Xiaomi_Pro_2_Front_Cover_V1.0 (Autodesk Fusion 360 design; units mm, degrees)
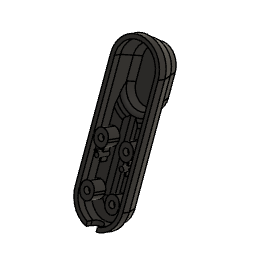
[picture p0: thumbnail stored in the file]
sketch "Skizze1" plane through (0, 0, 0) normal (0, 0, 1) x axis (1, 0, 0)
  line L1 (-32.75, -15) -> (32.75, -15)
  line L2 (32.75, 15) -> (-32.75, 15)
  line L3 (-47.75, 15) -> (47.75, -15)
  line L4 (47.75, 15) -> (-47.75, -15)
  arc A1 centre (-32.75, 0) radius 15 clockwise from (-47.75, 0) to (-32.75, 15)
  arc A2 centre (-32.75, 0) radius 15 clockwise from (-32.75, -15) to (-47.75, 0)
  arc A3 centre (32.75, 0) radius 15 clockwise from (32.75, 15) to (47.75, 0)
  arc A4 centre (32.75, 0) radius 15 clockwise from (47.75, 0) to (32.75, -15)
  point P6 (0, 0)
  point P1 (0, 0)
  point P4 (-47.75, 15)
  point P3 (-47.75, -15)
  point P8 (-47.75, 0)
  point P10 (-47.75, 0)
  point P5 (47.75, 15)
  point P2 (47.75, -15)
  point P14 (47.75, 0)
  point P16 (47.75, 0)
  horizontal L1
  parallel L1 L2
  coincident L3 P6
  coincident L4 P6
  coincident P1 P6
  coincident P4 L2
  tangent L2 A1
  coincident P3 L1
  tangent L1 A2
  coincident P8 P10
  coincident P5 L2
  tangent L2 A3
  coincident P2 L1
  tangent L1 A4
  coincident P14 P16
  dimension "d1" distance P4 P5 = 95.5
  dimension "d2" distance P3 P4 = 30
  dimension "d3" radius A1 = 15
  dimension "d4" radius A2 = 15
  dimension "d5" radius A3 = 15
  dimension "d6" radius A4 = 15
extrude "Extrusion1" new body sketch "Skizze1" profile of L1 L2 A1 A2 A3 A4 along normal blind 17
chamfer "Fase1" distance 5 distance 12.5
extrude "Extrusion2" cut of existing geometry blind -6 taper 22
sketch "Skizze2" plane through (0, 0, 11) normal (0, 0, 1) x axis (-1, 0, 0)
  line L1 (-32.75, 12.4) -> (32.75, 12.4)
  line L2 (32.75, -12.4) -> (-32.75, -12.4)
  line L3 (7.65, 0) -> (45.15, 0)
  line L4 (45.15, 12.4) -> (7.65, 12.4)
  line L5 (45.15, -12.4) -> (45.15, 12.4)
  line L6 (7.65, -12.4) -> (45.15, -12.4)
  line L7 (7.65, 12.4) -> (7.65, -12.4)
  line L8 (45.15, -12.4) -> (7.65, 12.4)
  line L9 (7.65, -12.4) -> (45.15, 12.4)
  line L10 (26.4, -12.4) -> (26.4, 0)
  line L11 (26.4, -12.4) -> (26.4, 0)
  arc A1 centre (-32.75, 0) radius 12.4 clockwise from (-32.75, -12.4) to (-32.75, 12.4)
  arc A2 centre (32.75, 0) radius 12.4 clockwise from (32.75, 12.4) to (32.75, -12.4)
  arc A3 centre (32.75, 0) radius 12.4 clockwise from (32.75, 12.4) to (32.75, -12.4)
  arc A4 centre (20.05, 0) radius 12.4 clockwise from (20.05, -12.4) to (20.05, 12.4)
  point P8 (45.15, 0)
  point P14 (26.4, 0)
  point P10 (7.65, 12.4)
  point P18 (26.4, 0)
  point P19 (26.4, -12.4)
  point P15 (32.75, -12.4)
  point P23 (20.05, -12.4)
  point P16 (32.75, 12.4)
  point P24 (20.05, 12.4)
  point P20 (26.4, 0)
  point P21 (26.4, -12.4)
  point P9 (7.65, 0)
  midpoint A2 P8
  horizontal L3
  horizontal L4
  perpendicular L4 L5
  parallel L4 L6
  parallel L5 L7
  coincident L8 P14
  coincident L9 P14
  coincident L1 P10
  midpoint L3 P14
  coincident P14 P18
  midpoint L6 P19
  symmetric P15 L10 P23
  symmetric P16 L10 P24
  symmetric A3 L10 A4
  symmetric P18 L10 P20
  symmetric P19 L10 P21
  dimension "d13" distance P8 P9 = 37.5
extrude "Extrusion3" add sketch "Skizze2" profile of L1 L2 A2 L3 L4 L6 A3 A4 along normal blind 6 taper -21.8
sketch "Skizze3" plane through (0, 0, 11) normal (0, 0, 1) x axis (-1, 0, 0)
  line L1 (-32.75, 12.4) -> (20.05, 12.4)
  line L2 (20.05, -12.4) -> (-32.75, -12.4)
  line L3 (13.0073, -11.4) -> (-32.75, -11.4)
  line L4 (-32.75, 11.4) -> (13.0073, 11.4)
  line L5 (-17, -4.5) -> (-17, 0)
  line L6 (7.4282, -4.5) -> (-17, -4.5)
  line L7 (-17, 4.5) -> (-17, 0)
  line L8 (7.4282, 4.5) -> (-17, 4.5)
  line L9 (-32.75, -4.5) -> (-17, -4.5)
  line L10 (-17, 4.5) -> (-32.75, 4.5)
  arc A1 centre (20.05, 0) radius 12.4 clockwise from (20.05, -12.4) to (20.05, 12.4)
  arc A2 centre (-32.75, 0) radius 12.4 clockwise from (-32.75, -12.4) to (-32.75, 12.4)
  arc A3 centre (20.05, 0) radius 13.4 clockwise from (13.0073, -11.4) to (13.0073, 11.4)
  arc A4 centre (-32.75, 0) radius 11.4 clockwise from (-32.75, -11.4) to (-32.75, 11.4)
  circle C1 centre (-32.75, 0) radius 4.5
  point P16 (7.4282, -4.5)
  point P18 (7.4282, 4.5)
  point P20 (-32.75, -4.5)
  point P21 (-32.75, 4.5)
  point P14 (-17, 0)
  point P15 (-17, -4.5)
  point P17 (-17, 4.5)
  perpendicular L3 L5
  coincident A3 P16
  perpendicular L5 L6
  perpendicular L6 L7
  coincident A3 P18
  perpendicular L7 L8
  concentric A2 C1
  coincident C1 P20
  tangent C1 L9
  perpendicular L5 L9
  coincident C1 P21
  tangent C1 L10
  dimension "d16" = -1
  dimension "d17" distance P14 P15 = 4.5
  dimension "d18" distance P14 P17 = 4.5
  dimension "d19" diameter C1 = 9
extrude "Extrusion4" cut sketch "Skizze3" profile of A3 L3 L4 A4 L6 L8 C1 L9 L10 against normal blind 1
fillet "Abrundung1" radius 0.5
fillet "Abrundung2" radius 0.5
shell "Schale" innerThickness 2.4
chamfer "Fase2" distance 1 distance 3
sketch "Skizze4" plane through (0, 0, 10) normal (0, 0, 1) x axis (-1, 0, 0)
  line L1 (-32.75, -4.5) -> (7.4282, -4.5)
  line L2 (7.4282, 4.5) -> (-32.75, 4.5)
  line L3 (-32.75, 11.4) -> (13.0073, 11.4)
  line L4 (13.0073, -11.4) -> (-32.75, -11.4)
  line L5 (-31.75, 0) -> (-47.75, 0)
  line L6 (-5.75, 0) -> (-31.75, 0)
  line L7 (7.4282, -4.5) -> (-32.75, -4.5)
  line L8 (-32.75, 4.5) -> (7.4282, 4.5)
  line L9 (-32.75, -11.4) -> (13.0073, -11.4)
  line L10 (13.0073, 11.4) -> (-32.75, 11.4)
  line L11 (-32.75, 7.9) -> (13.0073, 7.9)
  line L12 (13.0073, -7.9) -> (-32.75, -7.9)
  arc A1 centre (-32.75, 0) radius 4.5 clockwise from (-32.75, -4.5) to (-32.75, 4.5)
  arc A2 centre (20.05, 0) radius 13.4 clockwise from (7.4282, 4.5) to (13.0073, 11.4)
  arc A3 centre (-32.75, 0) radius 11.4 clockwise from (-32.75, -11.4) to (-32.75, 11.4)
  arc A4 centre (20.05, 0) radius 13.4 clockwise from (13.0073, -11.4) to (7.4282, -4.5)
  arc A5 centre (-32.75, 0) radius 15 clockwise from (-32.75, -15) to (-32.75, 15)
  arc A6 centre (-32.75, 0) radius 7.9 clockwise from (-32.75, -7.9) to (-32.75, 7.9)
  point P15 (-47.75, 0)
  point P31 (-5.75, -7.9)
  point P32 (-5.75, 7.9)
  point P33 (-31.75, -7.9)
  point P34 (-31.75, 7.9)
  point P16 (-31.75, 0)
  point P17 (-5.75, 0)
  midpoint A5 P15
  horizontal L5
  parallel L5 L6
  coincident L12 P31
  coincident L11 P32
  coincident L12 P33
  coincident L11 P34
  dimension "d31" distance P15 P16 = 16
  dimension "d32" distance P16 P17 = 26
  dimension "d33" = -3.5
sketch "Skizze5" plane through (0, 0, 7.6) normal (0, 0, -1) x axis (1, 0, 0)
  line L1 (-12.6556, 11.1751) -> (32.75, 11.1751)
  line L2 (32.75, 4.5) -> (-7.4282, 4.5)
  line L3 (-7.4282, -4.5) -> (32.75, -4.5)
  line L4 (32.75, -11.1751) -> (-12.6556, -11.1751)
  line L5 (5.025, 3.775) -> (6.475, 3.775)
  line L6 (0.875, 7.875) -> (0.875, 7.925)
  line L7 (6.475, 12.025) -> (5.025, 12.025)
  line L8 (10.625, 7.925) -> (10.625, 7.875)
  line L9 (0.875, 12.025) -> (10.625, 3.775)
  line L10 (10.625, 12.025) -> (0.875, 3.775)
  line L11 (32.475, 3.775) -> (31.025, 3.775)
  line L12 (36.625, 7.875) -> (36.625, 7.925)
  line L13 (31.025, 12.025) -> (32.475, 12.025)
  line L14 (26.875, 7.925) -> (26.875, 7.875)
  line L15 (36.625, 12.025) -> (26.875, 3.775)
  line L16 (26.875, 12.025) -> (36.625, 3.775)
  line L17 (5.025, -3.775) -> (6.475, -3.775)
  line L18 (0.875, -7.875) -> (0.875, -7.925)
  line L19 (6.475, -12.025) -> (5.025, -12.025)
  line L20 (10.625, -7.925) -> (10.625, -7.875)
  line L21 (0.875, -12.025) -> (10.625, -3.775)
  line L22 (10.625, -12.025) -> (0.875, -3.775)
  line L23 (31.025, -3.775) -> (32.475, -3.775)
  line L24 (26.875, -7.875) -> (26.875, -7.925)
  line L25 (32.475, -12.025) -> (31.025, -12.025)
  line L26 (36.625, -7.925) -> (36.625, -7.875)
  line L27 (26.875, -12.025) -> (36.625, -3.775)
  line L28 (36.625, -12.025) -> (26.875, -3.775)
  arc A1 centre (32.75, 0) radius 4.5 clockwise from (32.75, 4.5) to (32.75, -4.5)
  arc A2 centre (32.75, 0) radius 11.1751 clockwise from (32.75, 11.1751) to (32.75, -11.1751)
  arc A3 centre (5.025, 7.875) radius 4.15 clockwise from (0.875, 7.875) to (5.025, 12.025)
  arc A4 centre (5.025, 7.925) radius 4.15 clockwise from (5.025, 3.775) to (0.875, 7.925)
  arc A5 centre (6.475, 7.925) radius 4.15 clockwise from (10.625, 7.925) to (6.475, 3.775)
  arc A6 centre (6.475, 7.875) radius 4.15 clockwise from (6.475, 12.025) to (10.625, 7.875)
  arc A7 centre (31.025, 7.875) radius 4.15 clockwise from (26.875, 7.875) to (31.025, 12.025)
  arc A8 centre (32.475, 7.875) radius 4.15 clockwise from (32.475, 12.025) to (36.625, 7.875)
  arc A9 centre (32.475, 7.925) radius 4.15 clockwise from (36.625, 7.925) to (32.475, 3.775)
  arc A10 centre (31.025, 7.925) radius 4.15 clockwise from (31.025, 3.775) to (26.875, 7.925)
  arc A11 centre (32.475, -7.925) radius 4.15 clockwise from (32.475, -3.775) to (36.625, -7.925)
  arc A12 centre (32.475, -7.875) radius 4.15 clockwise from (36.625, -7.875) to (32.475, -12.025)
  arc A13 centre (31.025, -7.875) radius 4.15 clockwise from (31.025, -12.025) to (26.875, -7.875)
  arc A14 centre (31.025, -7.925) radius 4.15 clockwise from (26.875, -7.925) to (31.025, -3.775)
  arc A15 centre (6.475, -7.925) radius 4.15 clockwise from (6.475, -3.775) to (10.625, -7.925)
  arc A16 centre (5.025, -7.925) radius 4.15 clockwise from (0.875, -7.925) to (5.025, -3.775)
  arc A17 centre (5.025, -7.875) radius 4.15 clockwise from (5.025, -12.025) to (0.875, -7.875)
  arc A18 centre (6.475, -7.875) radius 4.15 clockwise from (10.625, -7.875) to (6.475, -12.025)
  arc A19 centre (-20.05, 0) radius 13.4 clockwise from (-12.6556, 11.1751) to (-7.4282, 4.5)
  arc A20 centre (-20.05, 0) radius 13.4 clockwise from (-7.4282, -4.5) to (-12.6556, -11.1751)
  point P19 (5.75, 7.9)
  point P12 (5.75, 7.9)
  point P24 (31.75, 7.9)
  point P11 (31.75, 7.9)
  point P29 (5.75, -7.9)
  point P13 (5.75, -7.9)
  point P34 (31.75, -7.9)
  point P14 (31.75, -7.9)
  point P17 (0.875, 12.025)
  point P16 (0.875, 3.775)
  point P15 (10.625, 3.775)
  point P18 (10.625, 12.025)
  point P23 (26.875, 12.025)
  point P22 (36.625, 12.025)
  point P21 (36.625, 3.775)
  point P20 (26.875, 3.775)
  point P30 (36.625, -3.775)
  point P33 (36.625, -12.025)
  point P32 (26.875, -12.025)
  point P31 (26.875, -3.775)
  point P25 (10.625, -3.775)
  point P26 (0.875, -3.775)
  point P27 (0.875, -12.025)
  point P28 (10.625, -12.025)
  horizontal L5
  perpendicular L5 L6
  parallel L5 L7
  parallel L6 L8
  coincident L9 P19
  coincident L10 P19
  coincident P12 P19
  horizontal L11
  perpendicular L11 L12
  parallel L11 L13
  parallel L12 L14
  coincident L15 P24
  coincident L16 P24
  coincident P11 P24
  horizontal L17
  perpendicular L17 L18
  parallel L17 L19
  parallel L18 L20
  coincident L21 P29
  coincident L22 P29
  coincident P13 P29
  horizontal L23
  perpendicular L23 L24
  parallel L23 L25
  parallel L24 L26
  coincident L27 P34
  coincident L28 P34
  coincident P14 P34
  coincident P17 L7
  coincident P17 L6
  tangent L7 A3
  tangent L6 A3
  coincident P16 L6
  coincident P16 L5
  tangent L6 A4
  tangent L5 A4
  equal A3 A4
  coincident P15 L5
  coincident P15 L8
  tangent L5 A5
  tangent L8 A5
  equal A3 A5
  coincident P18 L8
  coincident P18 L7
  tangent L8 A6
  tangent L7 A6
  equal A3 A6
  coincident P23 L14
  coincident P23 L13
  tangent L14 A7
  tangent L13 A7
  equal A3 A7
  coincident P22 L13
  coincident P22 L12
  tangent L13 A8
  tangent L12 A8
  equal A3 A8
  coincident P21 L12
  coincident P21 L11
  tangent L12 A9
  tangent L11 A9
  equal A3 A9
  coincident P20 L11
  coincident P20 L14
  tangent L11 A10
  tangent L14 A10
  equal A3 A10
  coincident P30 L23
  coincident P30 L26
  tangent L23 A11
  tangent L26 A11
  equal A3 A11
  coincident P33 L26
  coincident P33 L25
  tangent L26 A12
  tangent L25 A12
  equal A3 A12
  coincident P32 L25
  coincident P32 L24
  tangent L25 A13
  tangent L24 A13
  equal A3 A13
  coincident P31 L24
  coincident P31 L23
  tangent L24 A14
  tangent L23 A14
  equal A3 A14
  coincident P25 L20
  coincident P25 L17
  tangent L20 A15
  tangent L17 A15
  equal A3 A15
  coincident P26 L17
  coincident P26 L18
  tangent L17 A16
  tangent L18 A16
  equal A3 A16
  coincident P27 L18
  coincident P27 L19
  tangent L18 A17
  tangent L19 A17
  equal A3 A17
  coincident P28 L19
  coincident P28 L20
  tangent L19 A18
  tangent L20 A18
  equal A3 A18
  dimension "d39" distance P17 P18 = 9.75
  dimension "d40" distance P16 P17 = 8.25
  dimension "d41" distance P22 P23 = 9.75
  dimension "d42" distance P21 P22 = 8.25
  dimension "d43" distance P27 P28 = 9.75
  dimension "d44" distance P26 P27 = 8.25
  dimension "d45" distance P32 P33 = 9.75
  dimension "d46" distance P31 P32 = 8.25
  dimension "d47" radius A3 = 4.15
extrude "Extrusion5" add sketch "Skizze5" profile of L1 L2 A1 L3 L4 A2 L5 L7 L11 L13 L17 L19 L23 L25 A3 A4 A5 A6 A7 A8 A9 A10 A11 A12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 along normal blind 7.6 and against normal blind 1
sketch "Skizze6" plane through (0, 0, 0) normal (0, 0, -1) x axis (1, 0, 0)
  line L1 (-32.75, -12.6) -> (32.75, -12.6)
  line L2 (32.75, 12.6) -> (-32.75, 12.6)
  line L3 (32.75, -15) -> (-32.75, -15)
  line L4 (-32.75, 15) -> (32.75, 15)
  line L5 (5.025, 12.025) -> (6.475, 12.025)
  line L6 (31.025, 12.025) -> (32.475, 12.025)
  line L7 (32.475, -12.025) -> (31.025, -12.025)
  line L8 (6.475, -12.025) -> (5.025, -12.025)
  line L9 (5.375, 13.7209) -> (6.125, 13.7209)
  line L10 (5.375, 10.3291) -> (5.375, 13.7209)
  line L11 (6.125, 10.3291) -> (5.375, 10.3291)
  line L12 (6.125, 13.7209) -> (6.125, 10.3291)
  line L13 (5.375, 10.3291) -> (6.125, 13.7209)
  line L14 (6.125, 10.3291) -> (5.375, 13.7209)
  line L15 (6.125, 10.3291) -> (5.375, 13.7209)
  line L16 (5.375, 10.3291) -> (6.125, 13.7209)
  line L17 (5.375, 13.7209) -> (6.125, 13.7209)
  line L18 (5.375, 10.3291) -> (5.375, 13.7209)
  line L19 (6.125, 10.3291) -> (5.375, 10.3291)
  line L20 (6.125, 13.7209) -> (6.125, 10.3291)
  line L21 (31.375, 13.6) -> (32.125, 13.6)
  line L22 (31.375, 10.45) -> (31.375, 13.6)
  line L23 (32.125, 10.45) -> (31.375, 10.45)
  line L24 (32.125, 13.6) -> (32.125, 10.45)
  line L25 (31.375, 10.45) -> (32.125, 13.6)
  line L26 (32.125, 10.45) -> (31.375, 13.6)
  line L27 (31.375, -14) -> (32.125, -14)
  line L28 (31.375, -10.05) -> (31.375, -14)
  line L29 (32.125, -10.05) -> (31.375, -10.05)
  line L30 (32.125, -14) -> (32.125, -10.05)
  line L31 (31.375, -10.05) -> (32.125, -14)
  line L32 (32.125, -10.05) -> (31.375, -14)
  line L33 (5.375, -13.7758) -> (6.125, -13.7758)
  line L34 (5.375, -10.2742) -> (5.375, -13.7758)
  line L35 (6.125, -10.2742) -> (5.375, -10.2742)
  line L36 (6.125, -13.7758) -> (6.125, -10.2742)
  line L37 (5.375, -10.2742) -> (6.125, -13.7758)
  line L38 (6.125, -10.2742) -> (5.375, -13.7758)
  arc A1 centre (32.75, 0) radius 12.6 clockwise from (32.75, 12.6) to (32.75, -12.6)
  arc A2 centre (-32.75, 0) radius 12.6 clockwise from (-32.75, -12.6) to (-32.75, 12.6)
  arc A3 centre (-32.75, 0) radius 15 clockwise from (-32.75, -15) to (-32.75, 15)
  arc A4 centre (32.75, 0) radius 15 clockwise from (32.75, 15) to (32.75, -15)
  point P24 (5.75, 12.025)
  point P27 (5.75, 12.025)
  point P34 (31.75, 12.025)
  point P39 (31.75, -12.025)
  point P44 (5.75, -12.025)
  point P22 (5.375, 10.3291)
  point P23 (6.125, 10.3291)
  point P26 (5.375, 10.3291)
  point P28 (6.125, 10.3291)
  point P32 (31.375, 10.45)
  point P33 (32.125, 10.45)
  point P37 (31.375, -10.05)
  point P38 (32.125, -10.05)
  point P42 (5.375, -10.2742)
  point P43 (6.125, -10.2742)
  horizontal L9
  perpendicular L9 L10
  parallel L9 L11
  parallel L10 L12
  coincident L13 P24
  coincident L14 P24
  midpoint L5 P24
  horizontal L17
  perpendicular L17 L18
  parallel L17 L19
  parallel L18 L20
  coincident P27 L16
  coincident P27 L15
  horizontal L21
  perpendicular L21 L22
  parallel L21 L23
  parallel L22 L24
  coincident L25 P34
  coincident L26 P34
  midpoint L6 P34
  horizontal L27
  perpendicular L27 L28
  parallel L27 L29
  parallel L28 L30
  coincident L31 P39
  coincident L32 P39
  midpoint L7 P39
  horizontal L33
  perpendicular L33 L34
  parallel L33 L35
  parallel L34 L36
  coincident L37 P44
  coincident L38 P44
  midpoint L8 P44
  dimension "d52" distance P22 P23 = 0.75
  dimension "d53" distance P26 P28 = 0.75
  dimension "d54" distance P32 P33 = 0.75
  dimension "d55" distance P37 P38 = 0.75
  dimension "d56" distance P42 P43 = 0.75
extrude "Extrusion6" add sketch "Skizze6" profile of L1 L2 L5 L6 L7 L8 L9 L10 L11 L12 L17 L18 L19 L20 L21 L22 L23 L24 L27 L28 L29 L30 L33 L34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 against normal blind 6
sketch "Skizze7" plane through (0, 0, 0) normal (0, 0, -1) x axis (1, 0, 0)
  line L1 (-32.75, -12.6) -> (5.375, -12.6)
  line L2 (5.375, 12.6) -> (-32.75, 12.6)
  line L3 (5.375, 12.025) -> (5.375, 12.6)
  line L4 (5.025, 12.025) -> (5.375, 12.025)
  line L5 (6.475, 3.775) -> (5.025, 3.775)
  line L6 (6.125, 12.025) -> (6.475, 12.025)
  line L7 (6.125, 12.6) -> (6.125, 12.025)
  line L8 (31.375, 12.6) -> (6.125, 12.6)
  line L9 (31.375, 12.025) -> (31.375, 12.6)
  line L10 (31.025, 12.025) -> (31.375, 12.025)
  line L11 (32.475, 3.775) -> (31.025, 3.775)
  line L12 (32.125, 12.025) -> (32.475, 12.025)
  line L13 (32.125, 12.6) -> (32.125, 12.025)
  line L14 (32.75, 12.6) -> (32.125, 12.6)
  line L15 (32.125, -12.6) -> (32.75, -12.6)
  line L16 (32.125, -12.025) -> (32.125, -12.6)
  line L17 (32.475, -12.025) -> (32.125, -12.025)
  line L18 (31.025, -3.775) -> (32.475, -3.775)
  line L19 (31.375, -12.025) -> (31.025, -12.025)
  line L20 (31.375, -12.6) -> (31.375, -12.025)
  line L21 (6.125, -12.6) -> (31.375, -12.6)
  line L22 (6.125, -12.025) -> (6.125, -12.6)
  line L23 (6.475, -12.025) -> (6.125, -12.025)
  line L24 (5.025, -3.775) -> (6.475, -3.775)
  line L25 (5.375, -12.025) -> (5.025, -12.025)
  line L26 (5.375, -12.6) -> (5.375, -12.025)
  line L27 (32.75, -15) -> (-32.75, -15)
  line L28 (-32.75, 15) -> (32.75, 15)
  line L29 (14.25, 7.8744) -> (5.75, 7.9)
  line L30 (14.25, -7.8756) -> (5.75, -7.9)
  line L31 (13.8891, -12.7781) -> (13.875, -7.8766)
  line L32 (14.6391, -12.7781) -> (14.625, -7.8745)
  line L33 (13.8891, -12.7781) -> (14.6391, -12.7781)
  line L34 (9.9, -7.5006) -> (14.25, -7.5006)
  line L35 (9.9, -8.2631) -> (14.25, -8.2506)
  line L36 (9.9, -7.5006) -> (9.9, -8.2631)
  line L37 (14.6399, 12.8462) -> (14.625, 7.8733)
  line L38 (13.8899, 12.8462) -> (13.875, 7.8755)
  line L39 (14.6399, 12.8462) -> (13.8899, 12.8462)
  line L40 (9.8, 8.2494) -> (14.25, 8.2494)
  line L41 (9.8, 7.5128) -> (14.25, 7.4994)
  line L42 (9.8, 8.2494) -> (9.8, 7.5128)
  line L43 (18, -7.8673) -> (15.5, -7.8745)
  line L44 (18, -7.5006) -> (14.25, -7.5006)
  line L45 (18, -8.2506) -> (18, -7.5006)
  line L46 (14.25, -8.2506) -> (18, -8.2506)
  line L47 (14.25, -7.5006) -> (14.25, -8.2506)
  line L48 (18.1249, 7.8658) -> (15.625, 7.8733)
  line L49 (18.1249, 8.2494) -> (14.25, 8.2494)
  line L50 (18.1249, 7.4994) -> (18.1249, 8.2494)
  line L51 (14.25, 7.4994) -> (18.1249, 7.4994)
  line L52 (14.25, 8.2494) -> (14.25, 7.4994)
  arc A1 centre (-32.75, 0) radius 12.6 clockwise from (-32.75, -12.6) to (-32.75, 12.6)
  arc A2 centre (5.025, 7.875) radius 4.15 clockwise from (0.8751, 7.9) to (5.025, 12.025)
  arc A3 centre (5.025, 7.925) radius 4.15 clockwise from (5.025, 3.775) to (0.8751, 7.9)
  arc A4 centre (6.475, 7.925) radius 4.15 clockwise from (10.6249, 7.9) to (6.475, 3.775)
  arc A5 centre (6.475, 7.875) radius 4.15 clockwise from (6.475, 12.025) to (10.6249, 7.9)
  arc A6 centre (31.025, 7.875) radius 4.15 clockwise from (26.8751, 7.9) to (31.025, 12.025)
  arc A7 centre (31.025, 7.925) radius 4.15 clockwise from (31.025, 3.775) to (26.8751, 7.9)
  arc A8 centre (32.475, 7.925) radius 4.15 clockwise from (36.6249, 7.9) to (32.475, 3.775)
  arc A9 centre (32.475, 7.875) radius 4.15 clockwise from (32.475, 12.025) to (36.6249, 7.9)
  arc A10 centre (32.75, 0) radius 12.6 clockwise from (32.75, 12.6) to (32.75, -12.6)
  arc A11 centre (32.475, -7.875) radius 4.15 clockwise from (36.6249, -7.9) to (32.475, -12.025)
  arc A12 centre (32.475, -7.925) radius 4.15 clockwise from (32.475, -3.775) to (36.6249, -7.9)
  arc A13 centre (31.025, -7.925) radius 4.15 clockwise from (26.8751, -7.9) to (31.025, -3.775)
  arc A14 centre (31.025, -7.875) radius 4.15 clockwise from (31.025, -12.025) to (26.8751, -7.9)
  arc A15 centre (6.475, -7.875) radius 4.15 clockwise from (10.6249, -7.9) to (6.475, -12.025)
  arc A16 centre (6.475, -7.925) radius 4.15 clockwise from (6.475, -3.775) to (10.6249, -7.9)
  arc A17 centre (5.025, -7.925) radius 4.15 clockwise from (0.8751, -7.9) to (5.025, -3.775)
  arc A18 centre (5.025, -7.875) radius 4.15 clockwise from (5.025, -12.025) to (0.8751, -7.9)
  arc A19 centre (-32.75, 0) radius 15 clockwise from (-32.75, -15) to (-32.75, 15)
  arc A20 centre (32.75, 0) radius 15 clockwise from (32.75, 15) to (32.75, -15)
  circle C1 centre (14.25, 7.8744) radius 1.375
  circle C2 centre (14.25, -7.8756) radius 1.25
  circle C3 centre (14.25, 7.8744) radius 0.375
  circle C4 centre (14.25, -7.8756) radius 0.375
  point P69 (14.25, 7.8744)
  point P72 (14.25, 7.8744)
  point P71 (14.25, -7.8756)
  point P73 (14.25, -7.8756)
  point P76 (13.875, -7.8766)
  point P78 (14.625, -7.8745)
  point P80 (14.25, -7.5006)
  point P82 (14.25, -8.2506)
  point P84 (14.625, 7.8733)
  point P86 (13.875, 7.8755)
  point P88 (14.25, 8.2494)
  point P90 (14.25, 7.4994)
  point P92 (15.5, -7.8745)
  point P97 (15.625, 7.8733)
  point P68 (5.75, 7.9)
  point P70 (5.75, -7.9)
  point P93 (18, -7.8673)
  point P98 (18.1249, 7.8658)
  coincident P69 P72
  coincident P71 P73
  concentric C1 C3
  concentric C2 C4
  coincident C4 P76
  coincident L30 P76
  tangent C4 L31
  coincident C4 P78
  tangent C4 L32
  parallel L31 L32
  parallel L27 L33
  coincident C4 P80
  tangent C4 L34
  parallel L21 L34
  coincident C4 P82
  parallel L30 L35
  vertical L36
  coincident C3 P84
  tangent C3 L37
  coincident L29 P86
  coincident C3 P86
  tangent C3 L38
  parallel L8 L39
  coincident C3 P88
  tangent C3 L40
  horizontal L40
  coincident C3 P90
  parallel L29 L41
  perpendicular L40 L42
  coincident C2 P92
  perpendicular L32 L43
  horizontal L44
  vertical L45
  horizontal L46
  vertical L47
  coincident C1 P97
  perpendicular L37 L48
  horizontal L49
  vertical L50
  horizontal L51
  vertical L52
  dimension "d59" distance P68 P69 = 8.5
  dimension "d60" distance P70 P71 = 8.5
  dimension "d61" diameter C1 = 2.75
  dimension "d62" diameter C2 = 2.5
  dimension "d63" diameter C3 = 0.75
  dimension "d64" diameter C4 = 0.75
  dimension "d69" distance P92 P93 = 2.5
  dimension "d70" distance P97 P98 = 2.5
extrude "Extrusion7" add sketch "Skizze7" profile of A4 A5 L8 L21 A15 A16 L29 L30 C1 C2 C3 C4 L31 L32 L33 L34 L35 L36 L37 L38 L39 L40 L41 L42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 against normal blind 7.6
sketch "Skizze8" plane through (0, 0, 0) normal (0, 0, -1) x axis (1, 0, 0)
  line L1 (6.125, -12.6) -> (13.8885, -12.6)
  line L2 (6.125, -12.025) -> (6.125, -12.6)
  line L3 (6.475, -12.025) -> (6.125, -12.025)
  line L4 (13.0586, -8.254) -> (10.607, -8.261)
  line L5 (13.8885, -12.6) -> (13.8784, -9.0691)
  line L6 (14.6284, -9.0669) -> (14.6385, -12.6)
  line L7 (10.6032, -7.5006) -> (13.0575, -7.5006)
  line L8 (5.025, -3.775) -> (6.475, -3.775)
  line L9 (5.375, -12.025) -> (5.025, -12.025)
  line L10 (5.375, -12.6) -> (5.375, -12.025)
  line L11 (-32.75, -12.6) -> (5.375, -12.6)
  line L12 (5.375, 12.6) -> (-32.75, 12.6)
  line L13 (5.375, 12.025) -> (5.375, 12.6)
  line L14 (5.025, 12.025) -> (5.375, 12.025)
  line L15 (6.475, 3.775) -> (5.025, 3.775)
  line L16 (12.926, 7.5034) -> (10.6042, 7.5104)
  line L17 (14.6392, 12.6) -> (14.6289, 9.1962)
  line L18 (31.375, 12.6) -> (14.6392, 12.6)
  line L19 (31.375, 12.025) -> (31.375, 12.6)
  line L20 (31.025, 12.025) -> (31.375, 12.025)
  line L21 (32.475, 3.775) -> (31.025, 3.775)
  line L22 (32.125, 12.025) -> (32.475, 12.025)
  line L23 (32.125, 12.6) -> (32.125, 12.025)
  line L24 (32.75, 12.6) -> (32.125, 12.6)
  line L25 (32.125, -12.6) -> (32.75, -12.6)
  line L26 (32.125, -12.025) -> (32.125, -12.6)
  line L27 (32.475, -12.025) -> (32.125, -12.025)
  line L28 (31.025, -3.775) -> (32.475, -3.775)
  line L29 (31.375, -12.025) -> (31.025, -12.025)
  line L30 (31.375, -12.6) -> (31.375, -12.025)
  line L31 (14.6385, -12.6) -> (31.375, -12.6)
  line L32 (32.75, -15) -> (-32.75, -15)
  line L33 (-32.75, 15) -> (32.75, 15)
  line L34 (13.8789, 9.1984) -> (13.8892, 12.6)
  line L35 (10.6081, 8.2494) -> (12.9271, 8.2494)
  line L36 (6.125, 12.025) -> (6.475, 12.025)
  line L37 (6.125, 12.6) -> (6.125, 12.025)
  line L38 (13.8892, 12.6) -> (6.125, 12.6)
  line L39 (12.9271, 8.2494) -> (10.6081, 8.2494)
  line L40 (12.926, 7.5034) -> (10.6042, 7.5104)
  line L41 (13.8892, 12.6) -> (13.8789, 9.1984)
  line L42 (15.5728, 7.4994) -> (14.6392, 12.6)
  line L43 (14.6392, 12.6) -> (13.8892, 12.6)
  line L44 (10.6032, -7.5006) -> (15.4424, -8.2506)
  line L45 (13.0586, -8.254) -> (10.607, -8.261)
  line L46 (13.8885, -12.6) -> (13.8784, -9.0691)
  line L47 (13.8885, -12.6) -> (14.6385, -12.6)
  line L48 (14.6284, -9.0669) -> (14.6385, -12.6)
  line L49 (18.1249, 7.4994) -> (15.5728, 7.4994)
  line L50 (18.1249, 8.2494) -> (18.1249, 7.4994)
  line L51 (15.5728, 8.2494) -> (18.1249, 8.2494)
  line L52 (18, -8.2506) -> (15.4424, -8.2506)
  line L53 (18, -7.5006) -> (18, -8.2506)
  line L54 (15.4424, -7.5006) -> (18, -7.5006)
  arc A1 centre (6.475, -7.875) radius 4.15 clockwise from (10.607, -8.261) to (6.475, -12.025)
  arc A2 centre (14.25, -7.8756) radius 1.25 clockwise from (13.8784, -9.0691) to (13.0586, -8.254)
  arc A3 centre (14.25, -7.8756) radius 1.25 clockwise from (15.4424, -8.2506) to (14.6284, -9.0669)
  arc A4 centre (6.475, -7.925) radius 4.15 clockwise from (6.475, -3.775) to (10.6032, -7.5006)
  arc A5 centre (5.025, -7.925) radius 4.15 clockwise from (0.8751, -7.9) to (5.025, -3.775)
  arc A6 centre (5.025, -7.875) radius 4.15 clockwise from (5.025, -12.025) to (0.8751, -7.9)
  arc A7 centre (-32.75, 0) radius 12.6 clockwise from (-32.75, -12.6) to (-32.75, 12.6)
  arc A8 centre (5.025, 7.875) radius 4.15 clockwise from (0.8751, 7.9) to (5.025, 12.025)
  arc A9 centre (5.025, 7.925) radius 4.15 clockwise from (5.025, 3.775) to (0.8751, 7.9)
  arc A10 centre (6.475, 7.925) radius 4.15 clockwise from (10.6042, 7.5104) to (6.475, 3.775)
  arc A11 centre (14.25, 7.8744) radius 1.375 clockwise from (15.5728, 7.4994) to (12.926, 7.5034)
  arc A12 centre (31.025, 7.875) radius 4.15 clockwise from (26.8751, 7.9) to (31.025, 12.025)
  arc A13 centre (31.025, 7.925) radius 4.15 clockwise from (31.025, 3.775) to (26.8751, 7.9)
  arc A14 centre (32.475, 7.925) radius 4.15 clockwise from (36.6249, 7.9) to (32.475, 3.775)
  arc A15 centre (32.475, 7.875) radius 4.15 clockwise from (32.475, 12.025) to (36.6249, 7.9)
  arc A16 centre (32.75, 0) radius 12.6 clockwise from (32.75, 12.6) to (32.75, -12.6)
  arc A17 centre (32.475, -7.875) radius 4.15 clockwise from (36.6249, -7.9) to (32.475, -12.025)
  arc A18 centre (32.475, -7.925) radius 4.15 clockwise from (32.475, -3.775) to (36.6249, -7.9)
  arc A19 centre (31.025, -7.925) radius 4.15 clockwise from (26.8751, -7.9) to (31.025, -3.775)
  arc A20 centre (31.025, -7.875) radius 4.15 clockwise from (31.025, -12.025) to (26.8751, -7.9)
  arc A21 centre (-32.75, 0) radius 15 clockwise from (-32.75, -15) to (-32.75, 15)
  arc A22 centre (32.75, 0) radius 15 clockwise from (32.75, 15) to (32.75, -15)
  arc A23 centre (14.25, 7.8744) radius 1.375 clockwise from (12.9271, 8.2494) to (13.8789, 9.1984)
  arc A24 centre (6.475, 7.875) radius 4.15 clockwise from (6.475, 12.025) to (10.6081, 8.2494)
  circle C1 centre (14.25, 7.8744) radius 1.375
  circle C2 centre (14.25, -7.8756) radius 1.25
  circle C3 centre (6.4835, 7.9013) radius 4.1392
  circle C4 centre (6.4965, -7.9012) radius 4.1262
  arc A25 centre (14.25, 7.8744) radius 1.375 clockwise from (14.6289, 9.1962) to (15.5728, 8.2494)
  arc A26 centre (14.25, -7.8756) radius 1.25 clockwise from (13.0575, -7.5006) to (15.4424, -7.5006)
  point P79 (10.6081, 8.2494)
  point P86 (10.6081, 8.2494)
  point P78 (12.9271, 8.2494)
  point P87 (12.9271, 8.2494)
  point P35 (10.6042, 7.5104)
  point P88 (10.6042, 7.5104)
  point P37 (12.926, 7.5034)
  point P89 (12.926, 7.5034)
  point P77 (13.8789, 9.1984)
  point P90 (13.8789, 9.1984)
  point P76 (13.8892, 12.6)
  point P91 (13.8892, 12.6)
  point P40 (14.6392, 12.6)
  point P92 (14.6392, 12.6)
  point P38 (15.5728, 7.4994)
  point P93 (15.5728, 7.4994)
  point P94 (13.8892, 12.6)
  point P13 (15.4424, -8.2506)
  point P95 (15.4424, -8.2506)
  point P14 (10.6032, -7.5006)
  point P96 (10.6032, -7.5006)
  point P6 (10.607, -8.261)
  point P97 (10.607, -8.261)
  point P8 (13.0586, -8.254)
  point P98 (13.0586, -8.254)
  point P9 (13.8784, -9.0691)
  point P99 (13.8784, -9.0691)
  point P2 (13.8885, -12.6)
  point P100 (13.8885, -12.6)
  point P11 (14.6385, -12.6)
  point P101 (14.6385, -12.6)
  point P12 (14.6284, -9.0669)
  point P102 (14.6284, -9.0669)
  point P82 (6.125, 12.025)
  point P15 (6.475, -3.775)
  concentric A11 C1
  concentric A2 C2
  coincident P79 P86
  coincident P78 P87
  coincident P35 P88
  coincident P37 P89
  coincident P77 P90
  coincident P76 P91
  coincident P40 P92
  coincident P38 P93
  coincident P76 P94
  coincident P13 P95
  coincident P14 P96
  coincident P6 P97
  coincident P8 P98
  coincident P9 P99
  coincident P2 P100
  coincident P11 P101
  coincident P12 P102
  coincident P86 C3
  coincident P35 C3
  coincident P82 C3
  coincident P96 C4
  coincident P97 C4
  coincident P15 C4
extrude "Extrusion8" cut sketch "Skizze8" profile of L4 L5 L6 L7 L16 L17 L34 L35 C1 C2 L39 L40 L41 L43 L44 L45 L46 L47 L48 C3 C4 L49 L50 L51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 against normal blind 3.5
hole "Bohrung" HoleDepth 16 HoleDiameter 3.6 TipAngle 180 CBDepth 6.75 CBDiameter 6.2
fillet "Abrundung5" radius 7.5
fillet "Abrundung6" radius 31.5
work_plane "Arbeitsebene" RotateAngle 0
sketch "Skizze9" plane through (47.75, 0, 0) normal (1, 0, 0) x axis (0, 1, 0)
  line L1 (0, 6.5) -> (0, 0)
  line L2 (-3.25, 0) -> (-3.25, 3.25)
  line L3 (3.25, 0) -> (-3.25, 0)
  line L4 (3.25, 3.25) -> (3.25, 0)
  line L5 (-3.25, 0) -> (3.25, 6.5)
  line L6 (3.25, 0) -> (-3.25, 6.5)
  arc A1 centre (0, 3.25) radius 3.25 clockwise from (-3.25, 3.25) to (0, 6.5)
  arc A2 centre (0, 3.25) radius 3.25 clockwise from (0, 6.5) to (3.25, 3.25)
  point P1 (0, 0)
  point P2 (0, 0)
  point P8 (0, 3.25)
  point P5 (-3.25, 6.5)
  point P4 (3.25, 6.5)
  point P9 (0, 6.5)
  point P12 (0, 6.5)
  point P3 (0, 6.5)
  point P6 (-3.25, 0)
  point P7 (3.25, 0)
  coincident P1 P2
  vertical L1
  parallel L2 L4
  coincident L5 P8
  coincident L6 P8
  midpoint L1 P8
  coincident P5 L2
  tangent L2 A1
  coincident P4 L4
  tangent L4 A2
  coincident P9 P12
  dimension "d78" distance P2 P3 = 6.5
  dimension "d79" distance P6 P7 = 6.5
  dimension "d80" radius A1 = 3.25
  dimension "d81" radius A2 = 3.25
extrude "Extrusion9" cut sketch "Skizze9" profile of L1 L2 L3 L4 A1 A2 against normal blind 9
move "Verschieben"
